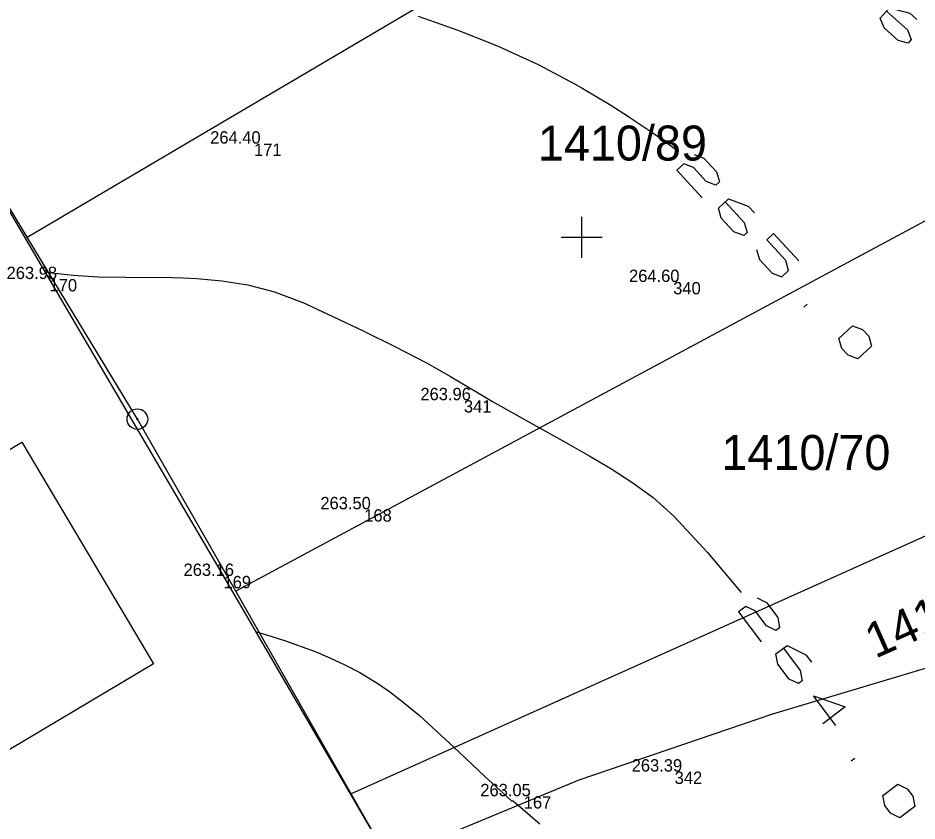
# Model space of a CAD drawing. Extents: x -771260 to -770828, y -1053564 to -1052811.
# Drawn here: x -771177.41 to -771133.69, y -1053278.38 to -1053239.34 of the extents above; entities that cross this region are included whole.
import ezdxf

# ---------------------------------------------------------------- set-up
doc = ezdxf.new("R2010")
doc.units = 0
for name, color, linetype in [('14_8_2023_krizky', 7, 'Continuous'), ('25_3_2019_krizky_JTSK', 7, 'Continuous'), ('25_3_2019_oploceni', 7, 'Continuous'), ('25_3_2019_vrstevnice_interval_po_1m', 7, 'Continuous'), ('25_3_2019_zamereny_bod', 7, 'Continuous'), ('25_3_2019_zamereny_bod_cislo', 7, 'Continuous'), ('25_3_2019_zamereny_bod_vyska', 7, 'Continuous'), ('Default', 7, 'Continuous'), ('DKM_Hranice parcel', 7, 'Continuous'), ('DKM_Parcelní čísla', 7, 'Continuous'), ('DKM_Značky bodu BP', 7, 'Continuous')]:
    doc.layers.add(name, color=color, linetype=linetype)

# ---------------------------------------------------------------- blocks, each defined once
blk = doc.blocks.new('POINT_DISPLAY')
at = {"layer": 'Default'}
blk.add_line((0, 0), (0, 0), dxfattribs=at)
blk = doc.blocks.new('KRIZEK')
at = {"layer": '25_3_2019_krizky_JTSK'}
for p, q in [((0, 10), (0, -10)), ((-10, 0), (10, 0))]:
    blk.add_line(p, q, dxfattribs=at)

msp = doc.modelspace()

# ---------------------------------------------------------------- linework, layer by layer
at = {"layer": '25_3_2019_oploceni'}
for p, q in [((-771175.871, -1053252.03), (-771184.958, -1053236.643)), ((-771167.412, -1053266.462), (-771175.871, -1053252.03)), ((-771159.56, -1053279.916), (-771167.412, -1053266.462))]:
    msp.add_line(p, q, dxfattribs=at)
at = {"layer": '25_3_2019_vrstevnice_interval_po_1m'}
for points in [[(-771135.176, -1053239.011), (-771134.16, -1053239.918), (-771133.973, -1053240.389), (-771134.124, -1053240.559), (-771134.614, -1053240.426), (-771135.291, -1053239.821), (-771135.479, -1053239.35), (-771135.025, -1053238.842), (-771134.046, -1053239.108), (-771133.707, -1053239.41)], [(-771157.943, -1053239.256), (-771156.303, -1053239.831), (-771155.937, -1053239.966), (-771154.227, -1053240.645), (-771153.991, -1053240.745), (-771152.112, -1053241.602), (-771150.314, -1053242.55), (-771149.943, -1053242.759), (-771148.587, -1053243.58), (-771147.726, -1053244.132), (-771147.713, -1053244.141), (-771146.541, -1053244.924), (-771145.332, -1053245.782)], [(-771156.303, -1053239.831), (-771156.303, -1053239.831)], [(-771155.937, -1053239.966), (-771155.937, -1053239.966)], [(-771154.227, -1053240.645), (-771154.227, -1053240.645)], [(-771153.991, -1053240.745), (-771153.991, -1053240.745)], [(-771152.112, -1053241.602), (-771152.112, -1053241.602)], [(-771150.314, -1053242.55), (-771150.314, -1053242.55)], [(-771149.943, -1053242.759), (-771149.943, -1053242.759)], [(-771148.587, -1053243.58), (-771148.587, -1053243.58)], [(-771147.713, -1053244.141), (-771147.713, -1053244.141)], [(-771146.541, -1053244.924), (-771146.541, -1053244.924)], [(-771144.537, -1053245.973), (-771144.062, -1053246.152), (-771143.445, -1053246.818), (-771143.303, -1053247.305), (-771143.47, -1053247.459), (-771143.944, -1053247.281), (-771144.561, -1053246.614), (-771145.036, -1053246.436), (-771145.369, -1053246.744), (-771144.136, -1053248.076)], [(-771143.019, -1053248.28), (-771142.094, -1053249.279), (-771141.952, -1053249.766), (-771142.119, -1053249.92), (-771142.594, -1053249.741), (-771143.211, -1053249.075), (-771143.352, -1053248.588), (-771142.853, -1053248.125), (-771141.903, -1053248.483), (-771141.595, -1053248.816)], [(-771141.502, -1053250.586), (-771141.36, -1053251.073), (-771140.744, -1053251.739), (-771140.269, -1053251.918), (-771139.936, -1053251.61), (-771140.078, -1053251.123), (-771141.003, -1053250.124), (-771140.67, -1053249.815), (-771139.436, -1053251.147)], [(-771176.06, -1053251.68), (-771176.06, -1053251.68)], [(-771176.06, -1053251.68), (-771175.764, -1053251.727), (-771175.761, -1053251.727), (-771175.48, -1053251.753), (-771175.456, -1053251.755), (-771174.722, -1053251.845), (-771173.507, -1053251.921), (-771172.162, -1053251.946), (-771169.917, -1053251.961), (-771169.376, -1053251.974), (-771168.712, -1053252.003), (-771167.487, -1053252.11), (-771166.234, -1053252.308), (-771164.94, -1053252.647), (-771163.605, -1053253.156), (-771163.592, -1053253.161), (-771162.096, -1053253.848), (-771160.592, -1053254.56), (-771159.079, -1053255.305), (-771157.549, -1053256.105), (-771156.913, -1053256.467), (-771156.382, -1053256.769), (-771155.062, -1053257.546), (-771154.332, -1053257.975), (-771152.349, -1053259.101), (-771150.616, -1053260.061), (-771149.595, -1053260.64), (-771148.574, -1053261.24), (-771147.553, -1053261.899), (-771146.531, -1053262.647), (-771145.515, -1053263.564), (-771145.509, -1053263.568), (-771143.876, -1053265.329), (-771142.242, -1053267.261)], [(-771175.764, -1053251.727), (-771175.764, -1053251.727)], [(-771175.48, -1053251.753), (-771175.48, -1053251.753)], [(-771174.722, -1053251.845), (-771174.722, -1053251.845)], [(-771173.507, -1053251.921), (-771173.507, -1053251.921)], [(-771172.162, -1053251.946), (-771172.162, -1053251.946)], [(-771169.917, -1053251.961), (-771169.917, -1053251.961)], [(-771169.376, -1053251.974), (-771169.376, -1053251.974)], [(-771168.712, -1053252.003), (-771168.712, -1053252.003)], [(-771167.487, -1053252.11), (-771167.487, -1053252.11)], [(-771166.234, -1053252.308), (-771166.234, -1053252.308)], [(-771164.94, -1053252.647), (-771164.94, -1053252.647)], [(-771163.592, -1053253.161), (-771163.592, -1053253.161)], [(-771139.202, -1053253.404), (-771139.035, -1053253.25)], [(-771162.096, -1053253.848), (-771162.096, -1053253.848)], [(-771137.351, -1053255.403), (-771137.493, -1053254.915), (-771136.827, -1053254.299), (-771136.352, -1053254.477), (-771136.044, -1053254.81), (-771135.902, -1053255.298), (-771136.568, -1053255.914), (-771137.043, -1053255.736), (-771137.351, -1053255.403)], [(-771160.592, -1053254.56), (-771160.592, -1053254.56)], [(-771159.079, -1053255.305), (-771159.079, -1053255.305)], [(-771157.549, -1053256.105), (-771157.549, -1053256.105)], [(-771156.382, -1053256.769), (-771156.382, -1053256.769)], [(-771154.332, -1053257.975), (-771154.332, -1053257.975)], [(-771152.349, -1053259.101), (-771152.349, -1053259.101)], [(-771150.616, -1053260.061), (-771150.616, -1053260.061)], [(-771149.595, -1053260.64), (-771149.595, -1053260.64)], [(-771148.574, -1053261.24), (-771148.574, -1053261.24)], [(-771147.553, -1053261.899), (-771147.553, -1053261.899)], [(-771146.531, -1053262.647), (-771146.531, -1053262.647)], [(-771145.509, -1053263.568), (-771145.509, -1053263.568)], [(-771143.876, -1053265.329), (-771143.876, -1053265.329)], [(-771141.47, -1053267.531), (-771141.015, -1053267.756), (-771140.468, -1053268.48), (-771140.375, -1053268.979), (-771140.556, -1053269.116), (-771141.011, -1053268.891), (-771141.558, -1053268.166), (-771142.013, -1053267.941), (-771142.375, -1053268.215), (-771141.28, -1053269.663)], [(-771165.808, -1053269.183), (-771165.808, -1053269.183)], [(-771165.808, -1053269.183), (-771165.118, -1053269.389), (-771164.4, -1053269.622), (-771162.961, -1053270.141), (-771162.239, -1053270.444), (-771161.515, -1053270.782), (-771160.788, -1053271.16), (-771160.064, -1053271.598), (-771160.058, -1053271.602), (-771159.337, -1053272.086), (-771158.598, -1053272.663), (-771157.884, -1053273.252), (-771156.42, -1053274.588), (-771155.977, -1053275.018), (-771154.711, -1053276.213), (-771153.406, -1053277.392), (-771153.358, -1053277.393), (-771153.329, -1053277.393), (-771153.314, -1053277.405), (-771153.199, -1053277.504), (-771152.035, -1053278.507)], [(-771165.118, -1053269.389), (-771165.118, -1053269.389)], [(-771164.4, -1053269.622), (-771164.4, -1053269.622)], [(-771140.19, -1053269.977), (-771139.369, -1053271.063), (-771139.276, -1053271.562), (-771139.457, -1053271.699), (-771139.912, -1053271.474), (-771140.459, -1053270.749), (-771140.552, -1053270.251), (-771140.009, -1053269.84), (-771139.099, -1053270.291), (-771138.826, -1053270.653)], [(-771162.961, -1053270.141), (-771162.961, -1053270.141)], [(-771162.239, -1053270.444), (-771162.239, -1053270.444)], [(-771161.515, -1053270.782), (-771161.515, -1053270.782)], [(-771160.788, -1053271.16), (-771160.788, -1053271.16)], [(-771160.058, -1053271.602), (-771160.058, -1053271.602)], [(-771159.337, -1053272.086), (-771159.337, -1053272.086)], [(-771158.598, -1053272.663), (-771158.598, -1053272.663)], [(-771137.635, -1053273.735), (-771138.729, -1053272.286), (-771137.184, -1053272.825), (-771138.27, -1053273.646)], [(-771157.884, -1053273.252), (-771157.884, -1053273.252)], [(-771156.42, -1053274.588), (-771156.42, -1053274.588)], [(-771155.977, -1053275.018), (-771155.977, -1053275.018)], [(-771136.902, -1053275.457), (-771136.721, -1053275.32)], [(-771154.711, -1053276.213), (-771154.711, -1053276.213)], [(-771135.26, -1053277.629), (-771135.353, -1053277.131), (-771134.629, -1053276.583), (-771134.174, -1053276.809), (-771133.9, -1053277.171), (-771133.808, -1053277.67), (-771134.532, -1053278.217), (-771134.987, -1053277.992), (-771135.26, -1053277.629)], [(-771153.406, -1053277.392), (-771153.406, -1053277.392)], [(-771153.329, -1053277.393), (-771153.329, -1053277.393)]]:
    msp.add_lwpolyline(points, dxfattribs=at)
at = {"layer": 'DKM_Hranice parcel'}
for p, q in [((-771176.96, -1053249.99), (-771134.3, -1053224.85)), ((-771176.96, -1053249.99), (-771185.04, -1053236.65)), ((-771122.61, -1053243.46), (-771166.82, -1053267.21)), ((-771114.64, -1053256.15), (-771161.21, -1053277.05)), ((-771161.21, -1053277.05), (-771166.82, -1053267.21)), ((-771159.39, -1053280.23), (-771161.21, -1053277.05))]:
    msp.add_line(p, q, dxfattribs=at)
for points in [[(-771166.82, -1053267.21), (-771171.6, -1053258.84), (-771176.96, -1053249.99)], [(-771114.64, -1053256.15), (-771110.79, -1053262.31), (-771110, -1053265.61), (-771121.4, -1053267.92), (-771131.13, -1053270.31), (-771140.72, -1053273.18), (-771150.13, -1053276.39), (-771159.39, -1053280.23)], [(-771170.82, -1053270.74), (-771181.66, -1053277.18), (-771187.99, -1053266.4), (-771177.22, -1053259.96), (-771170.82, -1053270.74)]]:
    msp.add_lwpolyline(points, dxfattribs=at)
at = {"layer": 'DKM_Značky bodu BP'}
for radius in [0.5, 0.0303]:
    msp.add_circle((-771171.6, -1053258.84), radius, dxfattribs=at)

# ---------------------------------------------------------------- block references
at = {"layer": '14_8_2023_krizky', "xscale": 0.1, "yscale": 0.10000000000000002}
msp.add_blockref('KRIZEK', (-771150, -1053250), dxfattribs=at)
at = {"layer": '25_3_2019_zamereny_bod', "xscale": 0.1, "yscale": 0.10000000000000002}
for p in [(-771165.929, -1053245.444), (-771175.871, -1053252.03), (-771145.549, -1053252.173), (-771155.724, -1053257.92), (-771160.572, -1053263.221), (-771167.413, -1053266.462), (-771145.477, -1053275.973), (-771152.814, -1053277.171)]:
    msp.add_blockref('POINT_DISPLAY', p, dxfattribs=at)

# ---------------------------------------------------------------- texts
at = {"layer": '25_3_2019_zamereny_bod_cislo'}
for s, p in [('171', (-771165.929, -1053246.044)), ('170', (-771175.871, -1053252.63)), ('340', (-771145.549, -1053252.773)), ('341', (-771155.724, -1053258.52)), ('168', (-771160.572, -1053263.821)), ('169', (-771167.413, -1053267.062)), ('342', (-771145.477, -1053276.573)), ('167', (-771152.814, -1053277.771))]:
    msp.add_text(s, height=0.6, dxfattribs=at).set_placement(p)
at = {"layer": '25_3_2019_zamereny_bod_vyska'}
for s, p in [('264.40 ', (-771168.062, -1053245.444)), ('263.98 ', (-771177.96, -1053252.03)), ('264.60 ', (-771147.697, -1053252.173)), ('263.96 ', (-771157.84, -1053257.92)), ('263.50 ', (-771162.704, -1053263.221)), ('263.16 ', (-771169.356, -1053266.462)), ('263.39 ', (-771147.567, -1053275.973)), ('263.05 ', (-771154.926, -1053277.171))]:
    msp.add_text(s, height=0.6, dxfattribs=at).set_placement(p)
at = {"layer": 'DKM_Parcelní čísla'}
for s, p in [('1410/89', (-771152.126, -1053246.269)), ('1410/70', (-771143.206, -1053261.31))]:
    msp.add_text(s, height=1.7, dxfattribs=at).set_placement(p)
msp.add_text('1410/53', height=1.7, rotation=24, dxfattribs=at).set_placement((-771135.724, -1053270.496))

doc.saveas('drawing.dxf')
